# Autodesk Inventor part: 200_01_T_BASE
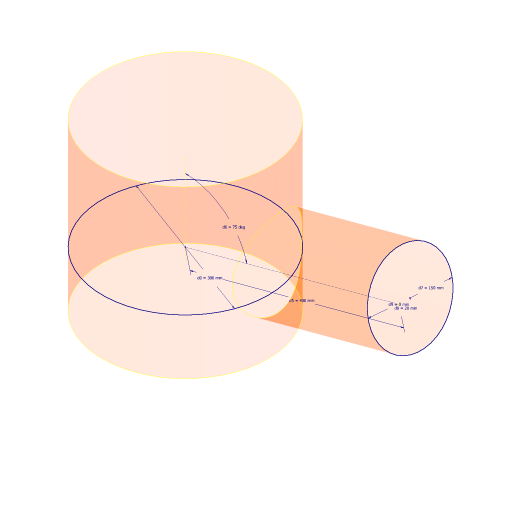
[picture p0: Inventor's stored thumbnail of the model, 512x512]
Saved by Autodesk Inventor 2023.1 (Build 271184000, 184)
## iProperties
Company: Fabian Stasiak CAD Consulting
Category: Autodesk® Inventor® Tutorial Series
Created: 2011-01
Part Number: 200_01_T_BASE
Document SubType Name: Sheet Metal
Designer: F.Stasiak
Density: 7.85 g/cm^3
Material: Steel
Appearance: Semi-Polished
Sheet Metal Rule: Steel 1.5 mm/Straight
Catalog Web Link: www.expertbooks.eu
Thickness: 1,500 mm
Author: F.Stasiak
Subject: Sheet Metal Design. Basic and Advanced techniques
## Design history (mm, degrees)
sketch "MAIN PIPE DIAMETER"
  geometry: C1 r 150 at (0, 0); 1 further point
  constraints: 1 centre point, 1 coincident
  dimensions: "d0" = 300 diameter of C1
feature "MAIN PIPE" dims "d1" = 200, "d2" = 100, "d3" = 0, "d4" = 0
sketch "ANGLE AND LENGHT SIED PIPE"
  geometry: L1 (0, 0)-(-386.37, 103.528); L2 (0, -24.192)-(0, 145.153) reference
  constraints: 2 end point
  dimensions: "d5" = 400 distance of L1.start L1.end; "d6" = 75 deg angle of L2 L1
node "Płaszczyzna konstrukcyjna1"
sketch "DIAMETER AND OFFSET OF SIDE PIPE"
  geometry: C1 r 75 at (20, 0); 1 further point
  constraints: 1 centre point
  dimensions: "d7" = 150 diameter of C1; "d8" = 20 distance of point (0, 0) C1.centre; "d9" = 0 vertical distance of C1.centre point (0, 0)
feature "SIDE PIPE" dims "d10" = 400 (= d5), "d11" = 0
feature "Utnij1"
feature "Utnij2"
body "Solid3"
body "Srf1"
body "Srf2"
other parameters: "Thickness" = 1.5 (derived), "WspółczynnikK" = 4.4, "BendRadius" = 1.5 (= Thickness), "BendReliefWidth" = 1.5 (= Thickness), "BendReliefDepth" = 0.75 (= 0.5 x Thickness), "CornerReliefSize" = 6 (= 4 x Thickness), "OdstępPołączenia" = 0.01, "MinimumRemnant" = 3 (= 2 x Thickness), "TransitionRadius" = 1.5 (= BendRadius), "JacobiRadiusSize" = 1.5 (= BendRadius), "GapSize" = 1.5 (= Thickness), "KFactor" = 4.4
